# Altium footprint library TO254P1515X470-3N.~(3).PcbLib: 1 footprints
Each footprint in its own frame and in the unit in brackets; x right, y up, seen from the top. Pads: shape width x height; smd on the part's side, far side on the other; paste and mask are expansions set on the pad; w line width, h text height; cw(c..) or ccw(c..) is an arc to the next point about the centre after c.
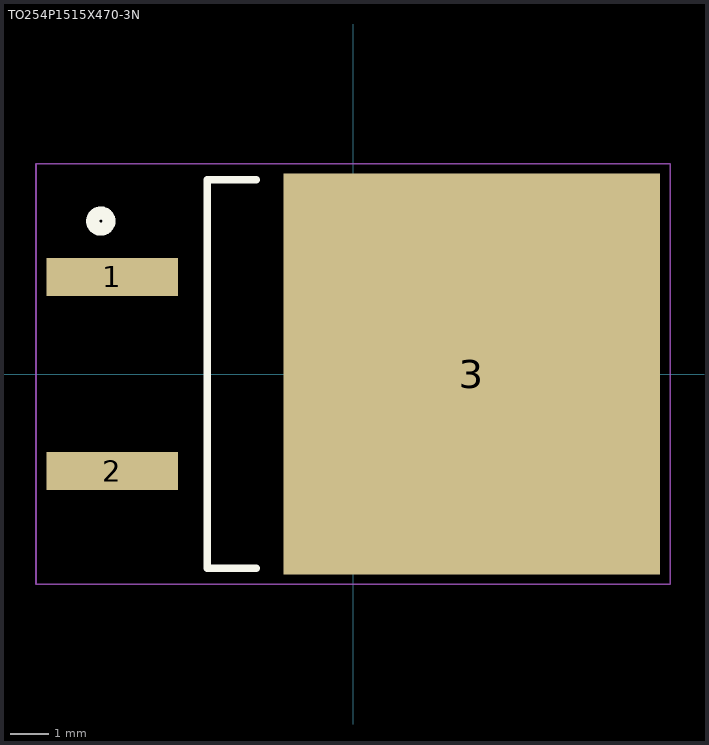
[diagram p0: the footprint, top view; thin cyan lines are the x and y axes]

## TO254P1515X470-3N [mm]
pads (3):
  rect 3.45x1 smd: 1(-6.3,2.54) 2(-6.3,-2.54)
  rect 9.85x10.5 smd: 3(3.1,0)
Top Overlay:
  circle w0.2: c-6.6,4 r0.283
  circle w0.2: c-6.6,4 r0.141
  lines w0.2: -2.54,-5.08 -3.81,-5.08 -3.81,5.08 -2.54,5.08
Top Paste:
  region: -0.68,4.76 0.68,4.76 0.68,3.24 -0.68,3.24
  region: 1.472,4.76 2.83,4.76 2.83,3.245 1.472,3.245
  region: 3.626,4.76 4.98,4.76 4.98,3.246 3.626,3.246
  region: 5.746,4.76 7.1,4.76 7.1,3.243 5.746,3.243
  region: -0.681,2.76 0.68,2.76 0.68,1.242 -0.681,1.242
  region: 1.471,2.76 2.83,2.76 2.83,1.241 1.471,1.241
  region: 3.624,2.76 4.98,2.76 4.98,1.241 3.624,1.241
  region: 5.75,2.76 7.1,2.76 7.1,1.242 5.75,1.242
  region: -0.681,0.76 0.68,0.76 0.68,-0.761 -0.681,-0.761
  region: 1.473,0.76 2.83,0.76 2.83,-0.761 1.473,-0.761
  region: 3.627,0.76 4.98,0.76 4.98,-0.761 3.627,-0.761
  region: 5.742,0.76 7.1,0.76 7.1,-0.76 5.742,-0.76
  region: -0.681,-1.24 0.68,-1.24 0.68,-2.763 -0.681,-2.763
  region: 1.471,-1.24 2.83,-1.24 2.83,-2.762 1.471,-2.762
  region: 3.622,-1.24 4.98,-1.24 4.98,-2.761 3.622,-2.761
  region: 5.741,-1.24 7.1,-1.24 7.1,-2.761 5.741,-2.761
  region: -0.681,-3.24 0.68,-3.24 0.68,-4.769 -0.681,-4.769
  region: 1.472,-3.24 2.83,-3.24 2.83,-4.767 1.472,-4.767
  region: 3.625,-3.24 4.98,-3.24 4.98,-4.766 3.625,-4.766
  region: 5.75,-3.24 7.1,-3.24 7.1,-4.768 5.75,-4.768
Mechanical 1:
  lines w0.05: -8.3,-5.5 8.3,-5.5 8.3,5.5 -8.3,5.5 -8.3,-5.5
